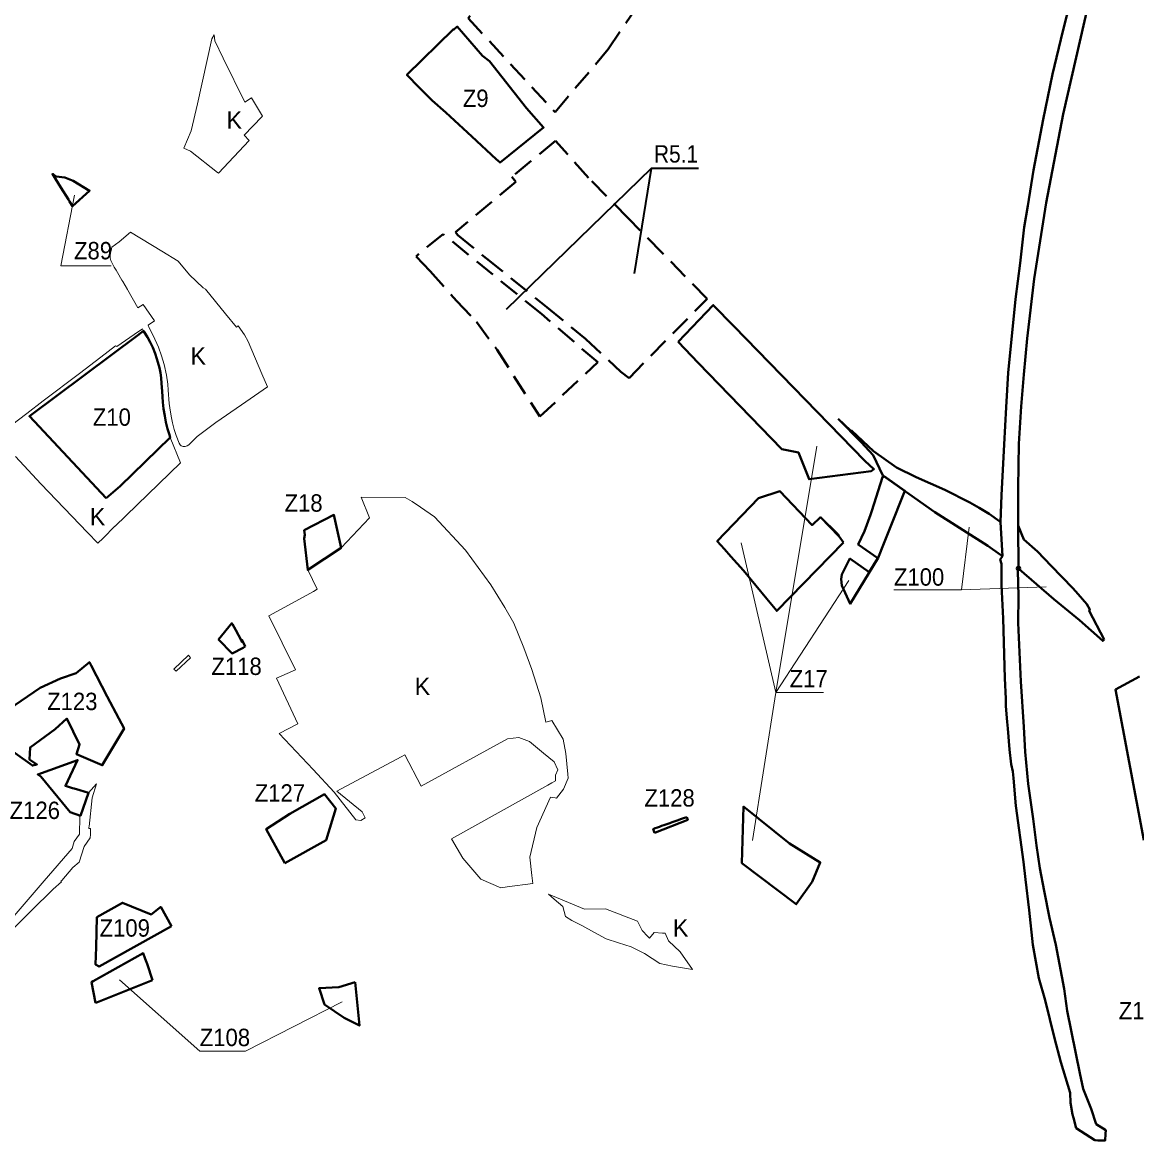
# Model space of a CAD drawing. Extents: x -650276 to -642489, y -1074311 to -1066658.
# Drawn here: x -646722 to -645184, y -1073293 to -1071749 of the extents above; entities that cross this region are included whole.
import ezdxf

# ---------------------------------------------------------------- set-up
doc = ezdxf.new("R2010")
doc.units = 0
doc.header["$LTSCALE"] = 9.6
doc.header["$PDMODE"] = 32
doc.header["$PDSIZE"] = 4.8
doc.linetypes.add('MEDIUM_DASHED', pattern=[4.5, 3, -1.5])
for name, color, linetype, lineweight in [('44', 7, 'Continuous', 40), ('45', 7, 'Continuous', 40), ('46', 7, 'Continuous', 13), ('47', 7, 'Continuous', 13), ('48', 7, 'Continuous', 13), ('61', 7, 'MEDIUM_DASHED', 40), ('62', 7, 'Continuous', 35)]:
    doc.layers.add(name, color=color, linetype=linetype, lineweight=lineweight)

msp = doc.modelspace()

# ---------------------------------------------------------------- linework, layer by layer
at = {"layer": '44'}
for points in [[(-645347.551, -1072443.527), (-645347.677, -1072391.355), (-645346.62, -1072330.914), (-645343.458, -1072278.998), (-645339.908, -1072235.158), (-645335.367, -1072185.207), (-645325.498, -1072102.789), (-645309.01, -1071998.147), (-645285.617, -1071875.733), (-645244.798, -1071696.585), (-645235.793, -1071663.703), (-645230.436, -1071634.261), (-645227.905, -1071625.277), (-645222.48, -1071606.08)], [(-645261.094, -1071645.025), (-645264.841, -1071657.687), (-645269.077, -1071687.396), (-645274.868, -1071717.176), (-645286.175, -1071761.228), (-645300.076, -1071820.179), (-645313.153, -1071883.081)], [(-645313.153, -1071883.081), (-645326.343, -1071952.807), (-645334.118, -1072001.954), (-645339.455, -1072031.565), (-645344.819, -1072081.225), (-645351.358, -1072130.815), (-645361.317, -1072232.824), (-645364.435, -1072280.268), (-645366.951, -1072331.609), (-645370.624, -1072401.447), (-645372.228, -1072438.764)], [(-645369.364, -1072485.931), (-645372.228, -1072438.764), (-645373.099, -1072438.135), (-645387.894, -1072427.453), (-645401.441, -1072419.033), (-645414.631, -1072411.611), (-645448.831, -1072394.325), (-645488.64, -1072376.782), (-645515.437, -1072363.447), (-645547.593, -1072340.827), (-645577.33, -1072312.704), (-645579.217, -1072312.425), (-645596.405, -1072296.114)], [(-645596.405, -1072296.114), (-645564.4, -1072328.61), (-645547.72, -1072346.19), (-645534.301, -1072374.332), (-645462.646, -1072425.015)], [(-645462.646, -1072425.015), (-645389.731, -1072471.612), (-645372.013, -1072484.069), (-645369.364, -1072485.931)], [(-645339.904, -1072462.677), (-645342.953, -1072455.042), (-645347.551, -1072443.527), (-645347.292, -1072502.877)], [(-645228.96, -1072600.865), (-645249.9, -1072561.25), (-645248.967, -1072559.511), (-645252.768, -1072552.178), (-645265.009, -1072538.358), (-645272.276, -1072530.154), (-645302.303, -1072499.014), (-645320.805, -1072479.495), (-645339.904, -1072462.677)], [(-645369.364, -1072485.931), (-645372.72, -1072490.314), (-645370.928, -1072496.619), (-645370.755, -1072525.734), (-645368.173, -1072571.881), (-645366.022, -1072654.462), (-645364.524, -1072682.575), (-645364.786, -1072692.977), (-645362.708, -1072714.781)], [(-645338.023, -1072755.969), (-645339.96, -1072721.587), (-645344.152, -1072658.857), (-645347.795, -1072577.893), (-645347.214, -1072540.97), (-645348.253, -1072505.583), (-645347.292, -1072502.877)], [(-645347.292, -1072502.877), (-645346.093, -1072503.921), (-645298.498, -1072545.352)], [(-645298.498, -1072545.352), (-645263.217, -1072574.314), (-645230.845, -1072602.888), (-645228.96, -1072600.865)], [(-645362.708, -1072714.781), (-645361.874, -1072723.527), (-645359.76, -1072752.865), (-645357.272, -1072772.771), (-645355.121, -1072782.993)], [(-645317.65, -1072916.642), (-645322.284, -1072885.085), (-645327.091, -1072848.387), (-645333.718, -1072799.987), (-645338.023, -1072755.969)], [(-645355.121, -1072782.993), (-645354.019, -1072792.454), (-645350.822, -1072830.388), (-645340.345, -1072908.029), (-645337.34, -1072932.073), (-645332.517, -1072974.538), (-645327.554, -1073022.214), (-645319.052, -1073068.6), (-645310.558, -1073098.946), (-645297.395, -1073151.294), (-645288.647, -1073184.518), (-645276.125, -1073226.571), (-645275.269, -1073240.71), (-645272.747, -1073256.762), (-645271.518, -1073261.16)], [(-645304.24, -1072985.372), (-645311.772, -1072947.945), (-645317.65, -1072916.642)], [(-645257.842, -1073221.36), (-645262.388, -1073199.409), (-645279.878, -1073113.356), (-645284.269, -1073083.286), (-645295.788, -1073022.556), (-645304.24, -1072985.372)], [(-645237.524, -1073292.361), (-645227.744, -1073292.735), (-645227.199, -1073283.366), (-645226.847, -1073278.345), (-645239.9, -1073270.025), (-645247.051, -1073248.736), (-645257.842, -1073221.36)], [(-645271.518, -1073261.16), (-645267.525, -1073275.443), (-645241.72, -1073292.2), (-645237.524, -1073292.361)]]:
    msp.add_lwpolyline(points, dxfattribs=at)
msp.add_lwpolyline([(-646652.18, -1071967.73), (-646629.655, -1071981.343), (-646653.198, -1072002.544), (-646657.32, -1071995.98), (-646658.79, -1071993.62), (-646669.31, -1071976.77), (-646676.79, -1071964.97), (-646681.07, -1071958.16), (-646675.99, -1071961.64), (-646663.87, -1071963.26)], close=True, dxfattribs=at)
at = {"layer": '44', "lineweight": 13}
for points in [[(-646599.686, -1072084.891), (-646669.193, -1072084.891), (-646650.508, -1071987.658)], [(-646599.686, -1072084.891), (-646669.193, -1072084.891), (-646650.508, -1071987.658)], [(-645519.31, -1072532.095), (-645425.882, -1072532.095), (-645415.202, -1072445.813), (-645425.882, -1072532.095), (-645309.26, -1072527.964)], [(-645519.31, -1072532.095), (-645425.882, -1072532.095), (-645415.202, -1072445.813), (-645425.882, -1072532.095), (-645309.26, -1072527.964)]]:
    msp.add_lwpolyline(points, dxfattribs=at)
at = {"layer": '44'}
msp.add_point((-645347.292, -1072502.877), dxfattribs=at)
at = {"layer": '45'}
msp.add_line((-646417.787, -1072612.168), (-646414.77, -1072610.61), dxfattribs=at)
for points in [[(-646102.04, -1071906.4), (-646068.317, -1071937.555), (-646062.91, -1071942.55), (-646002.93, -1071893.984), (-646026.64, -1071867.44), (-646043.49, -1071845.87), (-646077.32, -1071802.59), (-646087, -1071795), (-646104.5, -1071774.86), (-646122.16, -1071754.78), (-646127.12, -1071759.15), (-646127.84, -1071758.53), (-646191.57, -1071821.44), (-646174.69, -1071838.69), (-646156.59, -1071856.53), (-646137.74, -1071873.31)], [(-645817.219, -1072189.975), (-645768.649, -1072139.283), (-645740.45, -1072168.23), (-645559.34, -1072354.42), (-645546.82, -1072365.72), (-645550.41, -1072368.47), (-645636.37, -1072379.57), (-645650.78, -1072342.73), (-645674, -1072338), (-645789.298, -1072218.833)], [(-646606.848, -1072405.785), (-646587.666, -1072389.082), (-646518.208, -1072321.92), (-646519.417, -1072318.408), (-646522.007, -1072309.932), (-646524.282, -1072300.849), (-646526, -1072292.201), (-646527.5, -1072282.657), (-646528.566, -1072273.308), (-646529.182, -1072265.941), (-646529.607, -1072258.124), (-646530.188, -1072247.442), (-646530.892, -1072239.747), (-646531.93, -1072232.861), (-646533.286, -1072226.031), (-646535.344, -1072217.844), (-646536.772, -1072213.218), (-646539.168, -1072206.122), (-646539.168, -1072206.122), (-646542.484, -1072197.985), (-646546.09, -1072190.428), (-646549.793, -1072183.38), (-646554.56, -1072175.629), (-646555.051, -1072174.933), (-646563.299, -1072181.091), (-646710.684, -1072291.133), (-646712.634, -1072292.59)], [(-645503.98, -1072395.64), (-645532.75, -1072375.41), (-645535.05, -1072376.72), (-645549.6, -1072423.39), (-645551.54, -1072428.66), (-645559.92, -1072451.41), (-645568.38, -1072469.68), (-645541.56, -1072488.74), (-645553.35, -1072508.1), (-645579.92, -1072489.22), (-645581.13, -1072491), (-645591.06, -1072511.06), (-645592.08, -1072517.43), (-645591.03, -1072526.14), (-645579.76, -1072551.45), (-645541.09, -1072487.98), (-645533.15, -1072468.21), (-645524.87, -1072447.61)], [(-645588.78, -1072467), (-645594.83, -1072458.48), (-645596.43, -1072455.42), (-645620.56, -1072432), (-645632.1, -1072442.93), (-645676.53, -1072396.16), (-645706.039, -1072405.769), (-645763.06, -1072465.26), (-645753.128, -1072476.383), (-645744.38, -1072486.18), (-645726.95, -1072505.7), (-645709.92, -1072526.3), (-645694.51, -1072544.93), (-645680.87, -1072561.42)], [(-645588.78, -1072467), (-645594.83, -1072458.48), (-645620.56, -1072432), (-645632.1, -1072442.93), (-645676.53, -1072396.16), (-645706.039, -1072405.769), (-645763.06, -1072465.26), (-645753.128, -1072476.383), (-645744.38, -1072486.18), (-645726.95, -1072505.7), (-645709.92, -1072526.3), (-645694.51, -1072544.93), (-645680.87, -1072561.42)], [(-646333.34, -1072461.67), (-646328.45, -1072504.81), (-646282.47, -1072474.34), (-646292.44, -1072428.89), (-646333.33, -1072450.12), (-646332.68, -1072456.19)], [(-646333.34, -1072461.67), (-646328.45, -1072504.81), (-646282.47, -1072474.34), (-646292.44, -1072428.89), (-646333.33, -1072450.12), (-646332.68, -1072456.19)], [(-646360.22, -1072909.57), (-646303.02, -1072877.74), (-646289.63, -1072834.04), (-646305.56, -1072814.43), (-646353.25, -1072841.63), (-646385.86, -1072862.59)], [(-645729.36, -1072909.65), (-645654.16, -1072966.3), (-645632.23, -1072935.28), (-645620.92, -1072908.65), (-645663.52, -1072882.58), (-645726.9, -1072831.5)], [(-645729.36, -1072909.65), (-645654.16, -1072966.3), (-645632.23, -1072935.28), (-645620.92, -1072908.65), (-645663.52, -1072882.58), (-645726.9, -1072831.5)], [(-646516.7, -1072996.65), (-646531.46, -1072970.12), (-646544.68, -1072980.62), (-646584.23, -1072964.22), (-646619.48, -1072984.34), (-646620.71, -1073025.49), (-646621.44, -1073049.79), (-646616.55, -1073052.21)], [(-646516.7, -1072996.65), (-646531.46, -1072970.12), (-646544.68, -1072980.62), (-646584.23, -1072964.22), (-646619.48, -1072984.34), (-646620.71, -1073025.49), (-646621.44, -1073049.79), (-646616.55, -1073052.21)]]:
    msp.add_lwpolyline(points, close=True, dxfattribs=at)
for points in [[(-646420.36, -1072601.78), (-646427.95, -1072588.07), (-646432.57, -1072579.75), (-646433.36, -1072578.45), (-646451.458, -1072601.008), (-646433.024, -1072620.04), (-646417.787, -1072612.168)], [(-646414.77, -1072610.61), (-646419.11, -1072602.03), (-646419.47, -1072601.31), (-646419.02, -1072604.18), (-646420.36, -1072601.78)], [(-646737.05, -1072756.4), (-646732.5, -1072757.63), (-646708.65, -1072775.02), (-646702.45, -1072773.39), (-646712.46, -1072766.76), (-646711.79, -1072750.02), (-646677.39, -1072724.85), (-646660.89, -1072709.97), (-646643.36, -1072746.04), (-646647.93, -1072759.01), (-646612.11, -1072774.56), (-646581.92, -1072723.91), (-646589.37, -1072709.83), (-646605.23, -1072679.37), (-646627.32, -1072636.95), (-646629.86, -1072632.07), (-646648.27, -1072647.48), (-646669.6, -1072654.53), (-646697.89, -1072667.65)], [(-645180.05, -1072651.77), (-645213.34, -1072669.98), (-645174.13, -1072877.93)], [(-646697.89, -1072667.65), (-646732.95, -1072691.68), (-646759.491, -1072709.878), (-646757.5, -1072713.3), (-646747.87, -1072729.85), (-646744.94, -1072734.88), (-646748.3, -1072737.01), (-646737.05, -1072756.4)], [(-646653.02, -1072806.07), (-646663.07, -1072803.04), (-646663.07, -1072803.04), (-646646.12, -1072767.32), (-646646.31, -1072767.388), (-646701.12, -1072787.08), (-646697.09, -1072790.03), (-646656.36, -1072839.08)], [(-646656.36, -1072839.08), (-646642.404, -1072844.195), (-646631.08, -1072812.68), (-646643.01, -1072809.08), (-646651.11, -1072806.64), (-646653.02, -1072806.07)], [(-645849.703, -1072867.622), (-645848.52, -1072867.16), (-645803.84, -1072849.72), (-645805.159, -1072845.994)], [(-645805.159, -1072845.994), (-645808.177, -1072847.063), (-645811.148, -1072848.124), (-645813.978, -1072849.124), (-645816.948, -1072850.184), (-645819.779, -1072851.184), (-645822.726, -1072852.233), (-645825.527, -1072853.233), (-645828.409, -1072854.254), (-645834.208, -1072856.314)], [(-645834.208, -1072856.314), (-645837.027, -1072857.313), (-645839.908, -1072858.343), (-645842.74, -1072859.344), (-645845.619, -1072860.364), (-645848.628, -1072861.433), (-645851.48, -1072862.586), (-645850.187, -1072866.251), (-645850.17, -1072866.3), (-645849.705, -1072867.618), (-645849.703, -1072867.622)], [(-646542.62, -1073071.1), (-646550.01, -1073048.55), (-646552.79, -1073041.53), (-646555.79, -1073033.92), (-646624.69, -1073072.66), (-646626.967, -1073073.918), (-646621.38, -1073102.66)], [(-646542.62, -1073071.1), (-646550.01, -1073048.55), (-646552.79, -1073041.53), (-646555.79, -1073033.92), (-646624.69, -1073072.66), (-646626.967, -1073073.918), (-646621.38, -1073102.66)], [(-646542.62, -1073071.1), (-646550.01, -1073048.55), (-646552.79, -1073041.53), (-646555.79, -1073033.92), (-646624.69, -1073072.66), (-646626.967, -1073073.918), (-646621.38, -1073102.66)], [(-646542.62, -1073071.1), (-646550.01, -1073048.55), (-646552.79, -1073041.53), (-646555.79, -1073033.92), (-646624.69, -1073072.66), (-646626.967, -1073073.918), (-646621.38, -1073102.66)], [(-646621.38, -1073102.66), (-646620.19, -1073102.14), (-646618.56, -1073101.42), (-646542.62, -1073071.1)], [(-646621.38, -1073102.66), (-646620.19, -1073102.14), (-646618.56, -1073101.42), (-646542.62, -1073071.1)], [(-646621.38, -1073102.66), (-646620.19, -1073102.14), (-646618.56, -1073101.42), (-646542.62, -1073071.1)], [(-646621.38, -1073102.66), (-646620.19, -1073102.14), (-646618.56, -1073101.42), (-646542.62, -1073071.1)], [(-646262.94, -1073074.15), (-646285.77, -1073081.01), (-646312.87, -1073082.4), (-646305.18, -1073104.8), (-646278.38, -1073123.25)], [(-646262.94, -1073074.15), (-646285.77, -1073081.01), (-646312.87, -1073082.4), (-646305.18, -1073104.8), (-646278.38, -1073123.25)], [(-646278.38, -1073123.25), (-646257.09, -1073134.01), (-646262.94, -1073074.15)], [(-646278.38, -1073123.25), (-646257.09, -1073134.01), (-646262.94, -1073074.15)]]:
    msp.add_lwpolyline(points, dxfattribs=at)
at = {"layer": '46'}
for p, q in [((-645682.434, -1072673.943), (-645625.498, -1072333.934)), ((-645682.434, -1072673.943), (-645729.938, -1072467.657)), ((-645682.434, -1072673.943), (-645729.938, -1072467.657)), ((-645682.434, -1072673.943), (-645581.338, -1072519.311)), ((-645682.434, -1072673.943), (-645714.669, -1072878.528)), ((-645682.434, -1072673.943), (-645714.669, -1072878.528)), ((-645616.267, -1072673.943), (-645682.434, -1072673.943))]:
    msp.add_line(p, q, dxfattribs=at)
msp.add_lwpolyline([(-646588.523, -1073070.963), (-646477.555, -1073169.273), (-646414.561, -1073169.273), (-646281.126, -1073101.085)], dxfattribs=at)
msp.add_lwpolyline([(-646588.523, -1073070.963), (-646477.555, -1073169.273), (-646414.561, -1073169.273), (-646281.126, -1073101.085)], dxfattribs=at)
at = {"layer": '47'}
for p, q in [((-646490.111, -1071926.754), (-646453.04, -1071956.3)), ((-645882.07, -1073025.22), (-645863.39, -1073034.25))]:
    msp.add_line(p, q, dxfattribs=at)
for points in [[(-646453.04, -1071956.3), (-646451.87, -1071956.88), (-646409.4, -1071912.17), (-646416.2, -1071904.81), (-646391.83, -1071879.32), (-646390.732, -1071878.171), (-646405.99, -1071853.26), (-646415.46, -1071859.05), (-646445.115, -1071798.418), (-646456.96, -1071774.2), (-646457.52, -1071765.98), (-646461.09, -1071771.76), (-646480.81, -1071861.18), (-646489.34, -1071898.61), (-646499.741, -1071922.455), (-646490.111, -1071926.754)], [(-646507.28, -1072078.4), (-646530.073, -1072064.559), (-646573.05, -1072038.46), (-646588.75, -1072052.06), (-646598.827, -1072059.244), (-646599.86, -1072063.71), (-646601, -1072067.55), (-646601.42, -1072071.01), (-646601.16, -1072074.07), (-646600.8, -1072075.94), (-646600.22, -1072077.86), (-646598.67, -1072081.55), (-646595.86, -1072086.82), (-646593.13, -1072091.01), (-646591.02, -1072094.4), (-646585.08, -1072104.81), (-646583.9, -1072106.42), (-646577.41, -1072117.76), (-646577.08, -1072118.7), (-646563.11, -1072143.03), (-646555.49, -1072138.17), (-646539.94, -1072160.83), (-646548.676, -1072166.737)], [(-646472.72, -1072115.38), (-646491.69, -1072097.45), (-646507.28, -1072078.4)], [(-646426.98, -1072169.74), (-646441.961, -1072151.281), (-646469.41, -1072117.44), (-646472.72, -1072115.38)], [(-646548.676, -1072166.737), (-646547.606, -1072170.835), (-646541.822, -1072181.102), (-646534.527, -1072197.411), (-646530.167, -1072209.31), (-646526.798, -1072221.011), (-646523.628, -1072235.883)], [(-646415.84, -1072180.43), (-646424.56, -1072167.96), (-646426.98, -1072169.74)], [(-646731.82, -1072348.2), (-646696.83, -1072385.81), (-646632.356, -1072453.247), (-646618.158, -1072468.098), (-646611.091, -1072460.994), (-646594.606, -1072444.422), (-646594.561, -1072444.38), (-646504.244, -1072357.026), (-646518.208, -1072321.92), (-646587.666, -1072389.082), (-646606.848, -1072405.785), (-646712.634, -1072292.59), (-646563.299, -1072181.091), (-646556.591, -1072176.083), (-646555.051, -1072174.933), (-646556.693, -1072172.16), (-646568.051, -1072179.84), (-646592.2, -1072196.17), (-646593.85, -1072195.48), (-646614.075, -1072210.952), (-646643.55, -1072233.5), (-646693.58, -1072271.606), (-646716.167, -1072288.809), (-646737.449, -1072305.019)], [(-646391.77, -1072233.91), (-646410.68, -1072189.36), (-646415.84, -1072180.43)], [(-646523.628, -1072235.883), (-646523.628, -1072235.883), (-646521.646, -1072248.378), (-646521.051, -1072256.707), (-646519.756, -1072274.861), (-646518.079, -1072287.051), (-646516.692, -1072294.983), (-646515.305, -1072301.925), (-646512.729, -1072311.048), (-646509.954, -1072319.377), (-646506.189, -1072329.889), (-646504.802, -1072331.971), (-646503.018, -1072333.459), (-646500.244, -1072334.45), (-646497.569, -1072334.55), (-646494.794, -1072333.558), (-646492.813, -1072332.07), (-646486.273, -1072325.526), (-646480.923, -1072320.667), (-646462.79, -1072306.784), (-646455.557, -1072301.131), (-646420.085, -1072276.737), (-646384.056, -1072252.138), (-646391.77, -1072233.91)], [(-645999.622, -1072714.927), (-646006.66, -1072681.4), (-646019.16, -1072642.35), (-646030.17, -1072612.31), (-646043.87, -1072578.12), (-646056.42, -1072556.49), (-646075.82, -1072525.54), (-646110.61, -1072477.49), (-646153.49, -1072431.54), (-646172.81, -1072418.2), (-646184.449, -1072410.256), (-646194.19, -1072404.62), (-646254.75, -1072404.25), (-646243.17, -1072432.88), (-646282.47, -1072474.34), (-646328.45, -1072504.81), (-646315.452, -1072531.573)], [(-646315.452, -1072531.573), (-646320.62, -1072534.6), (-646350.18, -1072550.59), (-646382.41, -1072568.01), (-646345.6, -1072642.55), (-646368.51, -1072652.81), (-646371.66, -1072654.2), (-646342.08, -1072717.43), (-646367.72, -1072730.68), (-646321.171, -1072780.535), (-646292.17, -1072811.6), (-646261.97, -1072849.66), (-646255.39, -1072850.83), (-646249.04, -1072847.16), (-646253.56, -1072838.8), (-646288.27, -1072810.22), (-646199.72, -1072763.1), (-646194.296, -1072760.193)], [(-645969.46, -1072787.03), (-645972.31, -1072758.48), (-645975.86, -1072738.61), (-645991.31, -1072712.86), (-645996.31, -1072714.11), (-645999.622, -1072714.927)], [(-646194.296, -1072760.193), (-646171.72, -1072803.51), (-646052.58, -1072737.82), (-646037.23, -1072736.38), (-646022.4, -1072741.58), (-646003.22, -1072757.85), (-645988.43, -1072769.93), (-645983.22, -1072780.88), (-645986.24, -1072788.33), (-645986.359, -1072796.127)], [(-646732.95, -1072998.07), (-646710.3, -1072975.31), (-646680.07, -1072945.74), (-646668.53, -1072935.52), (-646669.198, -1072934.569), (-646668.09, -1072933.43), (-646652.76, -1072915.66), (-646644.069, -1072908.218), (-646644.061, -1072908.209), (-646644.059, -1072908.208), (-646637.2, -1072886.57), (-646628.7, -1072874.5), (-646628.58, -1072869.88), (-646628.36, -1072861.71), (-646630.76, -1072861.61), (-646630.57, -1072859.99), (-646630.45, -1072858.93), (-646625.91, -1072819.66), (-646620.27, -1072799.95), (-646631.08, -1072812.68), (-646640.313, -1072838.394), (-646642.404, -1072844.195), (-646642.39, -1072844.2), (-646642.438, -1072844.29), (-646642.939, -1072845.68), (-646643.574, -1072869.57), (-646650.798, -1072879.828), (-646653.846, -1072889.44), (-646692.432, -1072934.135), (-646739.241, -1072988.798)], [(-645986.359, -1072796.127), (-645991.37, -1072798.84), (-645996.8, -1072801.88), (-646129.91, -1072876.24), (-646114.5, -1072902.8), (-646089.39, -1072931.92), (-646062.04, -1072943.58), (-646053.287, -1072942.399), (-646017.65, -1072937.59), (-646019.21, -1072926.91), (-646021.64, -1072901.6), (-646012.37, -1072860.3), (-645993.47, -1072818.44), (-645986.71, -1072819.26), (-645985.19, -1072819.72), (-645975.3, -1072807.37)], [(-645975.3, -1072807.37), (-645969.01, -1072792.28), (-645969.46, -1072787.03)], [(-645866.93, -1073002.72), (-645873.3, -1072989.79), (-645917.53, -1072972.93), (-645946.4, -1072973.05), (-645996.2, -1072952.69)], [(-645996.2, -1072952.69), (-645988.49, -1072959.28), (-645976.48, -1072969.55), (-645972.6, -1072983.41)], [(-645972.6, -1072983.41), (-645963.77, -1072989), (-645962.81, -1072989.45), (-645949.85, -1072995.57), (-645932.44, -1073005.5), (-645916.47, -1073014.03), (-645899.35, -1073019.65), (-645882.07, -1073025.22)], [(-645838.89, -1073006.18), (-645850.37, -1073005.42), (-645856.46, -1073013.07), (-645858.82, -1073010.74), (-645866.93, -1073002.72)], [(-645863.39, -1073034.25), (-645842.53, -1073048.19), (-645824.93, -1073051.83), (-645797.32, -1073056.62), (-645814.27, -1073032.11), (-645830.6, -1073016.92)], [(-645830.6, -1073016.92), (-645834.9, -1073006.45), (-645838.89, -1073006.18)]]:
    msp.add_lwpolyline(points, dxfattribs=at)
msp.add_lwpolyline([(-646493.229, -1072622.74), (-646513.209, -1072641.935), (-646510.28, -1072644.42), (-646490.11, -1072626.15)], close=True, dxfattribs=at)
at = {"layer": '61'}
for points in [[(-645909.13, -1071478.56), (-645989, -1071611), (-646107, -1071743), (-645987.026, -1071872.902), (-645913.616, -1071786.041), (-645835.644, -1071670.191), (-645768.62, -1071540.17)], [(-645896.15, -1072231.57), (-645884.949, -1072239.96), (-645777.057, -1072130.664), (-645839.31, -1072066.947), (-645885.655, -1072019.486), (-645940.8, -1071963.54), (-645986.568, -1071912.301), (-646046.78, -1071962.265), (-646041.113, -1071969.094), (-646124.568, -1072038.344), (-646121.403, -1072042.471), (-646081.78, -1072075), (-645998.22, -1072142.19), (-645945, -1072186)], [(-646141.703, -1072041.072), (-646178.915, -1072071.95), (-646159.66, -1072092.31), (-646123.06, -1072133.18), (-646095.44, -1072162.47), (-646067.08, -1072201.18), (-646008.065, -1072293.22), (-645928.101, -1072218.151), (-646005.793, -1072151.499)]]:
    msp.add_lwpolyline(points, close=True, dxfattribs=at)
at = {"layer": '62'}
msp.add_line((-645854.421, -1071950.737), (-645877.767, -1072095.485), dxfattribs=at)
msp.add_lwpolyline([(-645789.051, -1071950.737), (-645854.421, -1071950.737), (-646054.422, -1072145.291)], dxfattribs=at)

# ---------------------------------------------------------------- texts
at = {"layer": '44', "width": 0.95}
for s, p in [('Z89', (-646651.144, -1072076.059)), ('Z89', (-646651.144, -1072076.059)), ('Z100', (-645519.262, -1072526.583)), ('Z100', (-645519.262, -1072526.583))]:
    msp.add_text(s, height=24, dxfattribs=at).set_placement(p)
at = {"layer": '46', "width": 0.95}
for s, p in [('Z9', (-646114.385, -1071865.725)), ('Z10', (-646625.207, -1072305.81)), ('Z18', (-646360.479, -1072424.402)), ('Z118', (-646461.466, -1072649.857)), ('Z17', (-645663.172, -1072666.966)), ('Z123', (-646688.261, -1072698.34)), ('Z127', (-646401.702, -1072824.699)), ('Z128', (-645863.685, -1072831.559)), ('Z126', (-646740.041, -1072848.718)), ('Z109', (-646615.842, -1073011.142)), ('Z109', (-646615.842, -1073011.142)), ('Z115', (-645208.897, -1073125.218)), ('Z108', (-646477.565, -1073162.229)), ('Z108', (-646477.565, -1073162.229))]:
    msp.add_text(s, height=24, dxfattribs=at).set_placement(p)
at = {"layer": '48'}
for p in [(-646440.579, -1071895.779), (-646490.42, -1072221.403), (-646629.338, -1072443.411), (-646180.786, -1072677.559), (-646180.786, -1072677.559), (-645824.362, -1073011.011), (-645824.362, -1073011.011)]:
    msp.add_text('K', height=24, dxfattribs=at).set_placement(p)
at = {"layer": '62', "width": 0.9}
msp.add_text('R5.1', height=24, dxfattribs=at).set_placement((-645850.499, -1071942.459))

doc.saveas('drawing.dxf')
